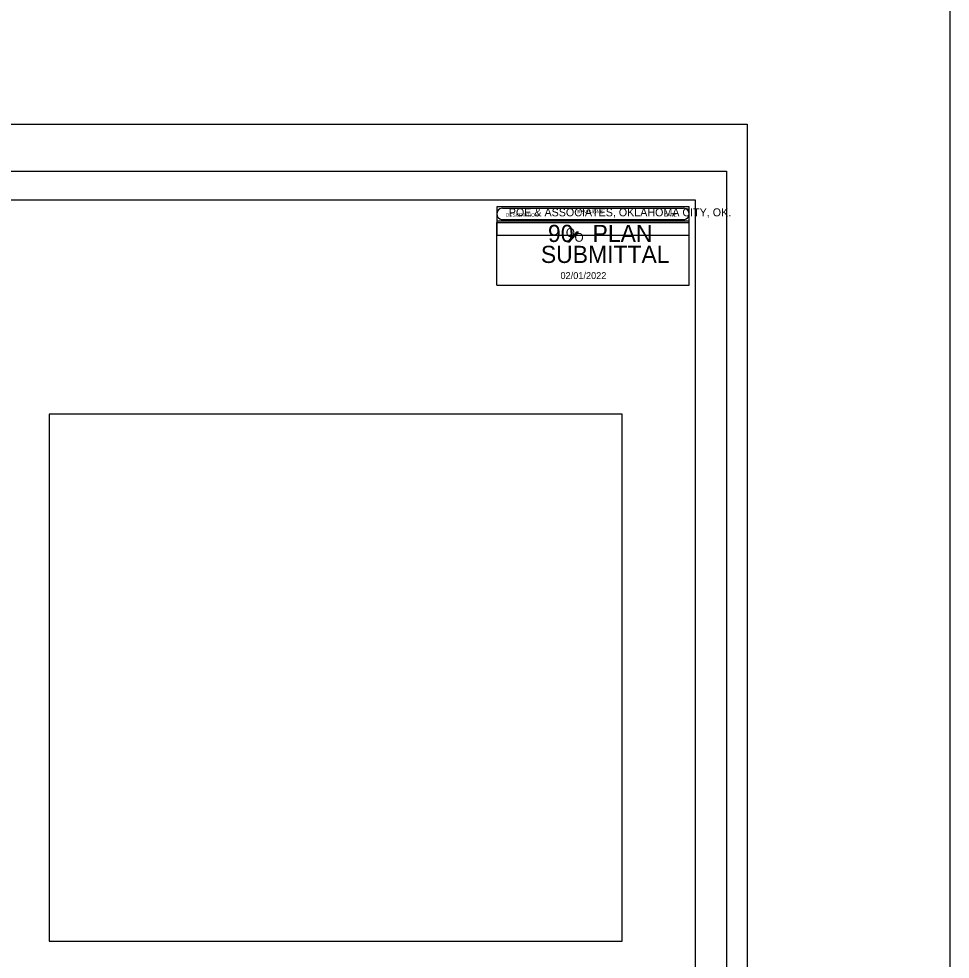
# Model space of a CAD drawing. Extents: x 12303.1 to 12355.9, y 579 to 640.5.
# Drawn here: x 12339.62 to 12355.91, y 593.99 to 610.44 of the extents above; entities that cross this region are included whole.
import ezdxf

# ---------------------------------------------------------------- set-up
doc = ezdxf.new("R2010")
doc.units = 0
for name, color, linetype in [('S', 7, 'Continuous'), ('SHT_Plot_Shape_Full', 7, 'Continuous'), ('SHT_Plot_Shape_Half', 7, 'Continuous'), ('SHT_Sheet_Border', 7, 'Continuous'), ('SHT_Stamp_90_Submit', 7, 'Continuous'), ('SHT_Stamp_Rev_Block', 7, 'Continuous'), ('T', 7, 'Continuous')]:
    doc.layers.add(name, color=color, linetype=linetype)

msp = doc.modelspace()

# ---------------------------------------------------------------- linework, layer by layer
at = {"layer": 'S'}
msp.add_lwpolyline([(12355.912, 640.488), (12312.476, 640.488), (12312.476, 579.031), (12355.912, 579.031)], close=True, dxfattribs=at)
at = {"layer": 'SHT_Plot_Shape_Full'}
msp.add_lwpolyline([(12316.36, 608.6), (12352.36, 608.6), (12352.36, 584.6), (12316.36, 584.6)], close=True, dxfattribs=at)
at = {"layer": 'SHT_Plot_Shape_Half'}
msp.add_lwpolyline([(12317.998, 607.775), (12351.998, 607.775), (12351.998, 585.775), (12317.998, 585.775)], close=True, dxfattribs=at)
at = {"layer": 'SHT_Sheet_Border'}
msp.add_lwpolyline([(12351.448, 586.275), (12319.948, 586.275), (12319.948, 607.275), (12351.448, 607.275)], close=True, dxfattribs=at)
at = {"layer": 'SHT_Stamp_90_Submit'}
for p, q in [((12348.079, 607.13), (12351.245, 607.13)), ((12348.079, 606.93), (12351.245, 606.93)), ((12347.979, 606.88), (12351.345, 606.88)), ((12347.979, 605.781), (12347.979, 606.88)), ((12351.345, 605.781), (12351.345, 606.88)), ((12349.222, 606.542), (12349.377, 606.714)), ((12349.24, 606.542), (12349.395, 606.714)), ((12349.245, 606.542), (12349.4, 606.714)), ((12349.252, 606.542), (12349.408, 606.714)), ((12349.377, 606.714), (12349.408, 606.714)), ((12349.222, 606.542), (12349.252, 606.542)), ((12347.979, 605.781), (12351.345, 605.781))]:
    msp.add_line(p, q, dxfattribs=at)
for centre, start, end in [((12348.079, 607.03), 89.9952, 270), ((12351.245, 607.03), 270, 90.0048)]:
    msp.add_arc(centre, 0.1, start, end, dxfattribs=at)
at = {"layer": 'SHT_Stamp_Rev_Block'}
for p, q in [((12347.979, 607.151), (12347.979, 606.651)), ((12351.345, 607.151), (12347.979, 607.151)), ((12351.345, 606.651), (12351.345, 607.151)), ((12351.345, 606.901), (12347.979, 606.901)), ((12351.345, 606.651), (12347.979, 606.651))]:
    msp.add_line(p, q, dxfattribs=at)
at = {"layer": 'T'}
msp.add_lwpolyline([(12340.146, 594.302), (12350.174, 594.302), (12350.174, 603.524), (12340.146, 603.524)], close=True, dxfattribs=at)

# ---------------------------------------------------------------- texts
at = {"layer": 'SHT_Stamp_90_Submit'}
for s, height, p in [('POE & ASSOCIATES, OKLAHOMA CITY, OK.', 0.14, (12348.189, 606.987)), ('90   PLAN', 0.3, (12348.874, 606.538)), ('O', 0.153, (12349.187, 606.627)), ('O', 0.153, (12349.339, 606.542)), ('SUBMITTAL', 0.3, (12348.75, 606.171)), ('02/01/2022', 0.12, (12349.093, 605.89))]:
    msp.add_text(s, height=height, rotation=360, dxfattribs=at).set_placement(p)
at = {"layer": 'SHT_Stamp_Rev_Block'}
for s, p in [('REVISIONS', (12349.388, 607.038)), ('DESCRIPTION', (12348.139, 606.979)), ('DATE', (12350.908, 606.983))]:
    msp.add_text(s, height=0.06, dxfattribs=at).set_placement(p)

doc.saveas('drawing.dxf')
